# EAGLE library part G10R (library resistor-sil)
SIL RESISTOR
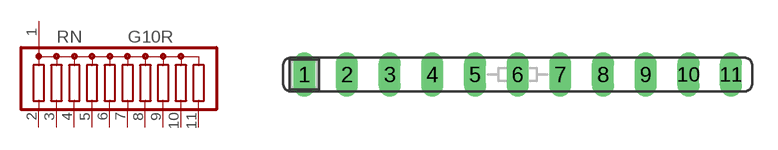
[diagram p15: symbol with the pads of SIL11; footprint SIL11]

Designator prefix RN

## G10R (OC_FARNELL: unknown; OC_NEWARK: unknown)  [SIL11]
1  1  pas
2  2  pas
3  3  pas
4  4  pas
5  5  pas
6  6  pas
7  7  pas
8  8  pas
9  9  pas
10  10  pas
11  11  pas

## Footprint SIL11 (pad centres in mm)
Single In Line
drill 0.813 long: 1 -12.7,0; 2 -10.16,0; 3 -7.62,0; 4 -5.08,0; 5 -2.54,0; 6 0,0; 7 2.54,0; 8 5.08,0; 9 7.62,0; 10 10.16,0; 11 12.7,0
